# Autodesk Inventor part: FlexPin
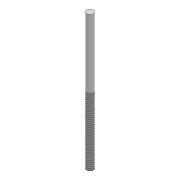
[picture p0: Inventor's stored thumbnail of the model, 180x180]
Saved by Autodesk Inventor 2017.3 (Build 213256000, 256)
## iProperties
Part Number: FlexPin
Material: 一般
Document SubType Name: Modeling
Designer: kyushu-hep
Density: 1 g/cm^3
Appearance: 既定
Author: kyushu-hep
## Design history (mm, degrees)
sketch "スケッチ1"
  geometry: C1 r 0.5 at (0, 0); 1 further point
  constraints: 1 centre point, 1 coincident
  dimensions: "d0" = 1 diameter of C1
extrude "押し出し1" new body sketch "スケッチ1" distance "d1" = 20; taper "d2" = 0 deg
feature "ねじ1" dims "d3" = 10, "d4" = 0
node "ソリッド1"
